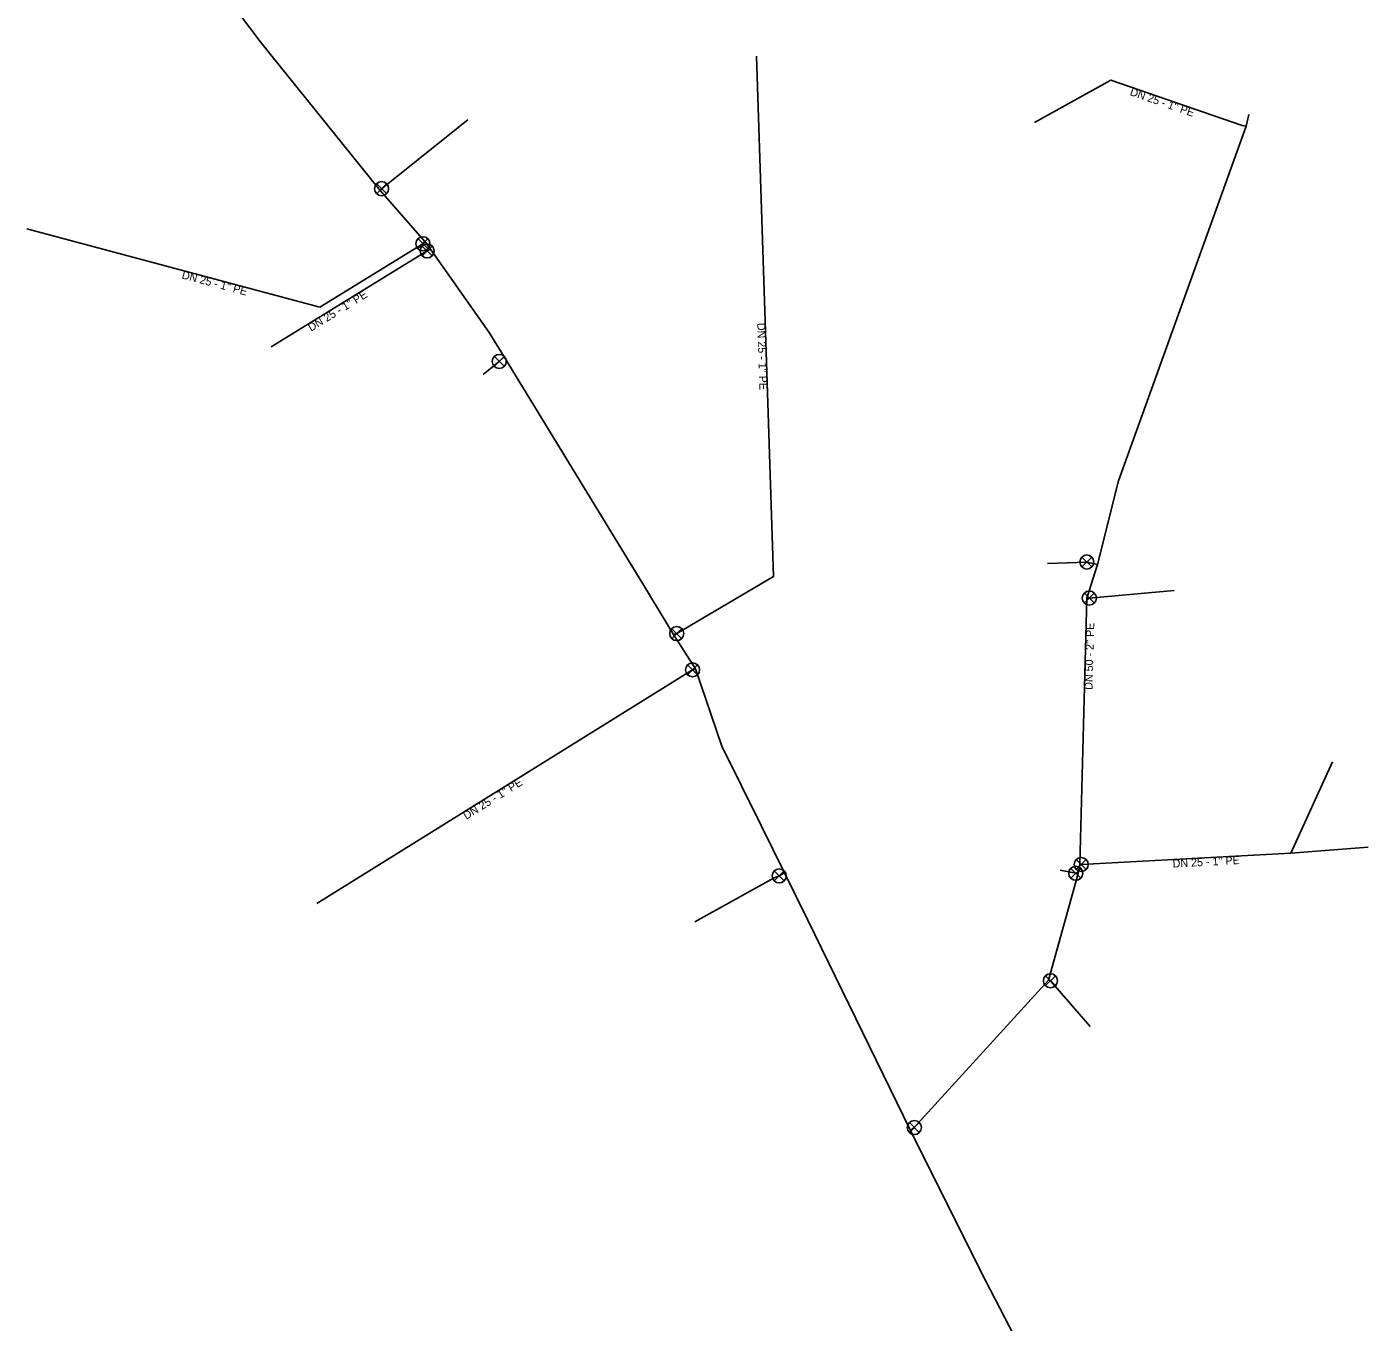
# Model space of a CAD drawing. Extents: x -484785 to -484462, y -1128039 to -1127627.
# Drawn here: x -484596.8 to -484520.5, y -1127947.3 to -1127873.7 of the extents above; entities that cross this region are included whole.
import ezdxf

# ---------------------------------------------------------------- set-up
doc = ezdxf.new("R2010")
doc.units = 0
for name, color, linetype in [('_pripojka_prevzato_z_dokumentace_', 7, 'Continuous'), ('_pripojka_priblizne_', 7, 'Continuous'), ('_voda_smvak_prevzato_z_dokumentace_', 7, 'Continuous'), ('Default', 7, 'Continuous'), ('MoLevel 32', 7, 'Continuous'), ('MoLevel 53', 7, 'Continuous'), ('MoLevel 55', 7, 'Continuous')]:
    doc.layers.add(name, color=color, linetype=linetype)

# ---------------------------------------------------------------- blocks, each defined once
blk = doc.blocks.new('_uzaver_pripojka_')
at = {"layer": 'Default'}
for p, q in [((-0.000035, -0.000035), (0.000035, 0.000035)), ((0.000035, -0.000035), (-0.000035, 0.000035))]:
    blk.add_line(p, q, dxfattribs=at)
for radius in [0.00005, 0.0000025]:
    blk.add_circle((0, 0), radius, dxfattribs=at)

msp = doc.modelspace()

# ---------------------------------------------------------------- linework, layer by layer
at = {"layer": '_pripojka_prevzato_z_dokumentace_'}
msp.add_line((-484524.916, -1127920.673), (-484522.545, -1127915.47), dxfattribs=at)
for points in [[(-484546.544, -1127936.43), (-484546.33, -1127936.27), (-484538.701, -1127927.883), (-484537.019, -1127921.831), (-484536.924, -1127921.296), (-484536.516, -1127906.17), (-484535.918, -1127904.248), (-484534.725, -1127899.495), (-484527.47, -1127879.326), (-484527.31, -1127878.658)], [(-484576.701, -1127882.989), (-484576.62, -1127882.88), (-484571.708, -1127878.966)], [(-484573.831, -1127886.311), (-484574.03, -1127886.42), (-484582.9, -1127891.88)], [(-484569.66, -1127892.439), (-484569.93, -1127892.7), (-484570.842, -1127893.448)], [(-484535.918, -1127904.248), (-484536.52, -1127904.11), (-484538.75, -1127904.198)], [(-484536.516, -1127906.17), (-484536.38, -1127906.16), (-484531.554, -1127905.733)], [(-484558.776, -1127910.175), (-484558.94, -1127910.24), (-484580.31, -1127923.53)], [(-484536.924, -1127921.296), (-484536.84, -1127921.31), (-484524.916, -1127920.673), (-484520.524, -1127920.326)], [(-484537.019, -1127921.831), (-484537.15, -1127921.81), (-484538.031, -1127921.633)], [(-484553.714, -1127921.778), (-484554.01, -1127921.96), (-484554.296, -1127922.078), (-484558.819, -1127924.573)], [(-484538.701, -1127927.883), (-484538.59, -1127927.918), (-484536.326, -1127930.531)]]:
    msp.add_lwpolyline(points, dxfattribs=at)
at = {"layer": '_pripojka_priblizne_'}
msp.add_line((-484580.128, -1127889.614), (-484596.793, -1127885.162), dxfattribs=at)
for points in [[(-484560.032, -1127908.228), (-484559.84, -1127908.18), (-484554.33, -1127904.937), (-484555.312, -1127875.352)], [(-484527.47, -1127879.326), (-484527.68, -1127879.29), (-484535.155, -1127876.709), (-484539.492, -1127879.119)], [(-484574.161, -1127885.888), (-484574.27, -1127886.01), (-484580.128, -1127889.614)]]:
    msp.add_lwpolyline(points, dxfattribs=at)
at = {"layer": '_voda_smvak_prevzato_z_dokumentace_'}
for points in [[(-484587.397, -1127869.371), (-484583.472, -1127874.589), (-484576.701, -1127882.989), (-484574.161, -1127885.888), (-484573.831, -1127886.311), (-484570.503, -1127891.062), (-484569.66, -1127892.439), (-484561.701, -1127905.445), (-484560.032, -1127908.228), (-484558.776, -1127910.175), (-484557.27, -1127914.59), (-484555.043, -1127919.092)], [(-484555.043, -1127919.092), (-484553.714, -1127921.778), (-484552.394, -1127924.476)], [(-484552.394, -1127924.476), (-484546.544, -1127936.43), (-484542.52, -1127944.486), (-484540.129, -1127949.131), (-484536.532, -1127956.516), (-484535.627, -1127958.307), (-484534.478, -1127960.474), (-484531.676, -1127963.881), (-484526.49, -1127971.83)]]:
    msp.add_lwpolyline(points, dxfattribs=at)

# ---------------------------------------------------------------- block references
at = {"layer": 'MoLevel 53', "xscale": 7999.999999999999, "yscale": 7999.999999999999}
for p in [(-484576.62, -1127882.88), (-484574.27, -1127886.01), (-484574.03, -1127886.42), (-484569.93, -1127892.7), (-484536.52, -1127904.11), (-484536.38, -1127906.16), (-484559.84, -1127908.18), (-484558.94, -1127910.24), (-484554.01, -1127921.96), (-484537.15, -1127921.81), (-484536.84, -1127921.31), (-484538.59, -1127927.92), (-484546.33, -1127936.27)]:
    msp.add_blockref('_uzaver_pripojka_', p, dxfattribs=at)

# ---------------------------------------------------------------- texts
at = {"layer": 'MoLevel 32'}
for rotation, p in [(340.95101, (-484534.104, -1127877.553)), (345.04291, (-484588.013, -1127887.979)), (271.9011, (-484555.264, -1127890.519))]:
    msp.add_text("DN 25 - 1'' PE", height=0.455, rotation=rotation, dxfattribs=at).set_placement(p)
at = {"layer": 'MoLevel 55'}
for s, rotation, p in [("DN 25 - 1'' PE", 31.61471, (-484580.63, -1127891.017)), ("DN 50 - 2'' PE", 88.45491, (-484536.201, -1127911.38)), ("DN 25 - 1'' PE", 31.87748, (-484571.803, -1127918.775)), ("DN 25 - 1'' PE", 3.05793, (-484531.628, -1127921.487))]:
    msp.add_text(s, height=0.455, rotation=rotation, dxfattribs=at).set_placement(p)

doc.saveas('drawing.dxf')
